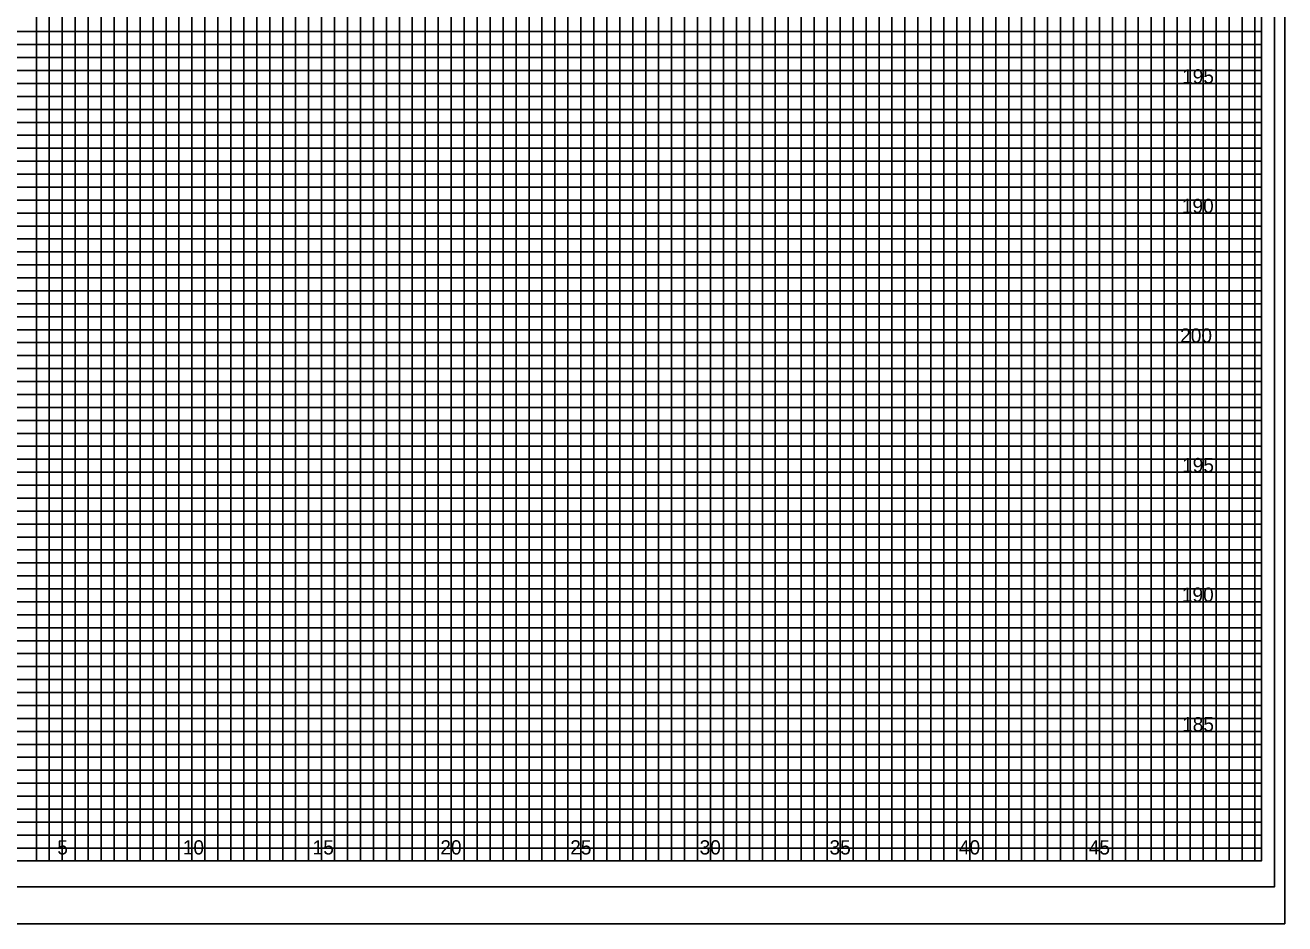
# Model space of a CAD drawing. Extents: x -4 to 103, y -2 to 209.
# Drawn here: x 54.82 to 103.4, y 68.4 to 103.08 of the extents above; entities that cross this region are included whole.
import ezdxf

# ---------------------------------------------------------------- set-up
doc = ezdxf.new("R2010")
doc.units = 0
for name, color, linetype in [('Exist XS Ground Line', 7, 'Continuous'), ('Old_Level_10', 7, 'Continuous'), ('Old_Level_3', 7, 'Continuous'), ('Old_Level_5', 7, 'Continuous'), ('Old_Level_8', 7, 'Continuous'), ('Prop XS Dump Level', 7, 'Continuous'), ('Prop XS Elevation Labels', 7, 'Continuous'), ('Prop XS Finish Grade', 7, 'Continuous'), ('Prop XS Label Text', 7, 'Continuous')]:
    doc.layers.add(name, color=color, linetype=linetype)

msp = doc.modelspace()

# ---------------------------------------------------------------- linework, layer by layer
at = {"layer": 'Exist XS Ground Line'}
msp.add_lwpolyline([(103, 136.825), (-2.8, 136.825), (-2.8, 69.825), (103, 69.825)], close=True, dxfattribs=at)
at = {"layer": 'Old_Level_10'}
for p, q in [((56.25, 70.825), (56.25, 135.825)), ((58.75, 70.825), (58.75, 135.825)), ((61.25, 70.825), (61.25, 135.825)), ((63.75, 70.825), (63.75, 135.825)), ((66.25, 70.825), (66.25, 135.825)), ((68.75, 70.825), (68.75, 135.825)), ((71.25, 70.825), (71.25, 135.825)), ((73.75, 70.825), (73.75, 135.825)), ((91.25, 70.825), (91.25, 134.25)), ((93.75, 70.825), (93.75, 134.25)), ((96.25, 70.825), (96.25, 134.25)), ((98.75, 70.825), (98.75, 134.25)), ((101.25, 70.825), (101.25, 134.25)), ((76.25, 70.825), (76.25, 132.825)), ((78.75, 70.825), (78.75, 132.825)), ((81.25, 70.825), (81.25, 132.825)), ((83.75, 70.825), (83.75, 132.825)), ((86.25, 70.825), (86.25, 132.825)), ((88.75, 70.825), (88.75, 132.825)), ((0, 100.825), (102.5, 100.825)), ((0, 98.325), (102.5, 98.325)), ((0, 95.825), (102.5, 95.825)), ((0, 93.325), (102.5, 93.325)), ((0, 90.825), (102.5, 90.825)), ((0, 88.325), (102.5, 88.325)), ((0, 85.825), (102.5, 85.825)), ((0, 83.325), (102.5, 83.325)), ((0, 80.825), (102.5, 80.825)), ((0, 78.325), (102.5, 78.325)), ((0, 75.825), (102.5, 75.825)), ((0, 73.325), (102.5, 73.325))]:
    msp.add_line(p, q, dxfattribs=at)
at = {"layer": 'Old_Level_3'}
msp.add_line((-3.5, 68.4), (103.4, 68.4), dxfattribs=at)
at = {"layer": 'Old_Level_5'}
msp.add_lwpolyline([(103.4, 138.225), (-3.5, 138.225), (-3.5, 68.4), (103.4, 68.4)], close=True, dxfattribs=at)
at = {"layer": 'Old_Level_8'}
for points in [[(56.25, 70.825), (56.25, 135.825)], [(58.75, 135.825), (58.75, 70.825), (61.25, 70.825), (61.25, 135.825)], [(63.75, 135.825), (63.75, 70.825), (66.25, 70.825), (66.25, 135.825)], [(68.75, 135.825), (68.75, 70.825), (71.25, 70.825), (71.25, 135.825)], [(73.75, 135.825), (73.75, 70.825), (76.25, 70.825), (76.25, 132.825)], [(88.75, 132.825), (88.75, 70.825), (91.25, 70.825), (91.25, 134.25)], [(93.75, 134.25), (93.75, 70.825), (96.25, 70.825), (96.25, 134.25)], [(98.75, 134.25), (98.75, 70.825), (101.25, 70.825), (101.25, 134.25)], [(78.75, 132.825), (78.75, 70.825), (81.25, 70.825), (81.25, 132.825)], [(83.75, 132.825), (83.75, 70.825), (86.25, 70.825), (86.25, 132.825)], [(0, 98.325), (102.5, 98.325), (102.5, 100.825), (0, 100.825)], [(0, 93.325), (102.5, 93.325), (102.5, 95.825), (0, 95.825)], [(0, 88.325), (102.5, 88.325), (102.5, 90.825), (0, 90.825)], [(0, 83.325), (102.5, 83.325), (102.5, 85.825), (0, 85.825)], [(0, 78.325), (102.5, 78.325), (102.5, 80.825), (0, 80.825)], [(0, 73.325), (102.5, 73.325), (102.5, 75.825), (0, 75.825)]]:
    msp.add_lwpolyline(points, dxfattribs=at)
at = {"layer": 'Prop XS Dump Level'}
msp.add_lwpolyline([(102.5, 135.825), (0, 135.825), (0, 70.825), (102.5, 70.825)], close=True, dxfattribs=at)
at = {"layer": 'Prop XS Finish Grade'}
for points in [[(54.75, 70.825), (55.25, 70.825), (55.25, 135.825)], [(55.75, 135.825), (55.75, 70.825), (56.75, 70.825), (56.75, 135.825)], [(57.25, 135.825), (57.25, 70.825), (57.75, 70.825), (57.75, 135.825)], [(58.25, 135.825), (58.25, 70.825), (59.25, 70.825), (59.25, 135.825)], [(59.75, 135.825), (59.75, 70.825), (60.25, 70.825), (60.25, 135.825)], [(60.75, 135.825), (60.75, 70.825), (61.75, 70.825), (61.75, 135.825)], [(62.25, 135.825), (62.25, 70.825), (62.75, 70.825), (62.75, 135.825)], [(63.25, 135.825), (63.25, 70.825), (64.25, 70.825), (64.25, 135.825)], [(64.75, 135.825), (64.75, 70.825), (65.25, 70.825), (65.25, 135.825)], [(65.75, 135.825), (65.75, 70.825), (66.75, 70.825), (66.75, 135.825)], [(67.25, 135.825), (67.25, 70.825), (67.75, 70.825), (67.75, 135.825)], [(68.25, 135.825), (68.25, 70.825), (69.25, 70.825), (69.25, 135.825)], [(69.75, 135.825), (69.75, 70.825), (70.25, 70.825), (70.25, 135.825)], [(70.75, 135.825), (70.75, 70.825), (71.75, 70.825), (71.75, 135.825)], [(72.25, 135.825), (72.25, 70.825), (72.75, 70.825), (72.75, 135.825)], [(73.25, 135.825), (73.25, 70.825), (74.25, 70.825), (74.25, 132.825)], [(89.75, 132.825), (89.75, 70.825), (90.25, 70.825), (90.25, 134.25)], [(90.75, 134.25), (90.75, 70.825), (91.75, 70.825), (91.75, 134.25)], [(92.25, 134.25), (92.25, 70.825), (92.75, 70.825), (92.75, 134.25)], [(93.25, 134.25), (93.25, 70.825), (94.25, 70.825), (94.25, 134.25)], [(94.75, 134.25), (94.75, 70.825), (95.25, 70.825), (95.25, 134.25)], [(95.75, 134.25), (95.75, 70.825), (96.75, 70.825), (96.75, 134.25)], [(97.25, 134.25), (97.25, 70.825), (97.75, 70.825), (97.75, 134.25)], [(98.25, 134.25), (98.25, 70.825), (99.25, 70.825), (99.25, 134.25)], [(99.75, 134.25), (99.75, 70.825), (100.25, 70.825), (100.25, 134.25)], [(100.25, 134.25), (100.75, 134.25), (100.75, 70.825), (101.75, 70.825), (101.75, 134.25), (102.25, 134.25), (102.25, 70.825)], [(74.75, 132.825), (74.75, 70.825), (75.25, 70.825), (75.25, 132.825)], [(75.75, 132.825), (75.75, 70.825), (76.75, 70.825), (76.75, 132.825)], [(77.25, 132.825), (77.25, 70.825), (77.75, 70.825), (77.75, 132.825)], [(78.25, 132.825), (78.25, 70.825), (79.25, 70.825), (79.25, 132.825)], [(79.75, 132.825), (79.75, 70.825), (80.25, 70.825), (80.25, 132.825)], [(80.75, 132.825), (80.75, 70.825), (81.75, 70.825), (81.75, 132.825)], [(82.25, 132.825), (82.25, 70.825), (82.75, 70.825), (82.75, 132.825)], [(83.25, 132.825), (83.25, 70.825), (84.25, 70.825), (84.25, 132.825)], [(84.75, 132.825), (84.75, 70.825), (85.25, 70.825), (85.25, 132.825)], [(85.75, 132.825), (85.75, 70.825), (86.75, 70.825), (86.75, 132.825)], [(87.25, 132.825), (87.25, 70.825), (87.75, 70.825), (87.75, 132.825)], [(88.25, 132.825), (88.25, 70.825), (89.25, 70.825), (89.25, 132.825)], [(0, 102.325), (102.5, 102.325), (102.5, 102.825), (0, 102.825)], [(0, 101.325), (102.5, 101.325), (102.5, 101.825), (0, 101.825)], [(0, 99.825), (102.5, 99.825), (102.5, 100.325), (0, 100.325)], [(0, 98.825), (102.5, 98.825), (102.5, 99.325), (0, 99.325)], [(0, 97.325), (102.5, 97.325), (102.5, 97.825), (0, 97.825)], [(0, 96.325), (102.5, 96.325), (102.5, 96.825), (0, 96.825)], [(0, 94.825), (102.5, 94.825), (102.5, 95.325), (0, 95.325)], [(0, 93.825), (102.5, 93.825), (102.5, 94.325), (0, 94.325)], [(0, 92.325), (102.5, 92.325), (102.5, 92.825), (0, 92.825)], [(0, 91.325), (102.5, 91.325), (102.5, 91.825), (0, 91.825)], [(0, 89.825), (102.5, 89.825), (102.5, 90.325), (0, 90.325)], [(0, 88.825), (102.5, 88.825), (102.5, 89.325), (0, 89.325)], [(0, 87.325), (102.5, 87.325), (102.5, 87.825), (0, 87.825)], [(0, 86.325), (102.5, 86.325), (102.5, 86.825), (0, 86.825)], [(0, 84.825), (102.5, 84.825), (102.5, 85.325), (0, 85.325)], [(0, 83.825), (102.5, 83.825), (102.5, 84.325), (0, 84.325)], [(0, 82.325), (102.5, 82.325), (102.5, 82.825), (0, 82.825)], [(0, 81.325), (102.5, 81.325), (102.5, 81.825), (0, 81.825)], [(0, 79.825), (102.5, 79.825), (102.5, 80.325), (0, 80.325)], [(0, 78.825), (102.5, 78.825), (102.5, 79.325), (0, 79.325)], [(0, 77.325), (102.5, 77.325), (102.5, 77.825), (0, 77.825)], [(0, 76.325), (102.5, 76.325), (102.5, 76.825), (0, 76.825)], [(0, 74.825), (102.5, 74.825), (102.5, 75.325), (0, 75.325)], [(0, 73.825), (102.5, 73.825), (102.5, 74.325), (0, 74.325)], [(0, 72.325), (102.5, 72.325), (102.5, 72.825), (0, 72.825)], [(0, 71.325), (102.5, 71.325), (102.5, 71.825), (0, 71.825)]]:
    msp.add_lwpolyline(points, dxfattribs=at)

# ---------------------------------------------------------------- texts
at = {"layer": 'Prop XS Elevation Labels'}
for s, p in [('5', (56.0574, 71.075)), ('10', (60.8971, 71.075)), ('15', (65.9057, 71.075)), ('20', (70.8312, 71.075)), ('25', (75.8399, 71.075)), ('30', (80.8312, 71.075)), ('35', (85.8399, 71.075)), ('40', (90.8313, 71.075)), ('45', (95.8399, 71.075))]:
    msp.add_text(s, height=0.55, dxfattribs=at).set_placement(p)
at = {"layer": 'Prop XS Label Text'}
for s, p in [('195', (99.4383, 100.825)), ('190', (99.4296, 95.825)), ('200', (99.3638, 90.825)), ('195', (99.4383, 85.825)), ('190', (99.4296, 80.825)), ('185', (99.4383, 75.825))]:
    msp.add_text(s, height=0.55, dxfattribs=at).set_placement(p)

doc.saveas('drawing.dxf')
